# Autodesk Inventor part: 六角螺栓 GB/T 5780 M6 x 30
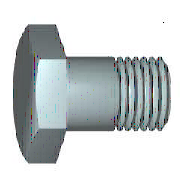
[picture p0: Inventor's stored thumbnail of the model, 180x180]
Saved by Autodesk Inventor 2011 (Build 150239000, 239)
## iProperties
IsCustomPart: 1
Created: 2010-02
Part Number: 六角螺栓 GB/T 5780 M6 x 30
Material: 低炭钢
Description: 六角头螺栓 - 产品等级 C
Document SubType Name: Modeling
Standard: GB/T 5780-2000
Designer: Administrator
Standard Revision: 2000
Standards Organization: GB
Language: zh-CN
Size Designation: M6x30
Categories: <MemberInstance><Categories><Category DisplayName="紧固件" InternalName="e4da775c-781d-43d5-af7c-5136215cf5a6" Mnemonic="FSTN"><Category DisplayName="螺栓" InternalN
Density: 1 g/cm^3
Author: Administrator
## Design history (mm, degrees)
fillet "Fillet2" dims "d71" = 0.25 (= RR)
workplane "Work Plane1"
sketch "Sketch1"
  geometry: L1 (0, 3)-(16, 3); L2 (16, 3)-(16, 0); L3 (16, 0)-(0, 0); L4 (-3.2, 0)-(19.2, 0) reference; L5 (0, -0.6)-(0, 3.6) reference; L6 (0, 3)-(0, 0)
  constraints: 8 end point, 3 point on line, 1 collinear
  dimensions: "d2" = 6 diameter of L1 L3 (= GD); "d59" = 16 distance between parallel lines of L2 L5
revolve "Body" sketch "Sketch1" stored, may be unused: angle "d12" = 90 deg
sketch "Sketch2"
  geometry: L1 (0, 5.774)-(5, 2.887); L2 (5, 2.887)-(5, -2.887); L3 (5, -2.887)-(0, -5.774); L4 (0, -5.774)-(-5, -2.887); L5 (-5, -2.887)-(-5, 2.887); L6 (-5, 2.887)-(0, 5.774); L7 (-7, 0)-(7, 0) reference; L8 (0, 8.083)-(0, -8.083) reference; 2 further points
  constraints: 12 end point, 2 midpoint, 1 coincident, 1 vertical, 11 other
  dimensions: "d11" = 10 distance between parallel lines of L5 L2 (= SW)
extrude "Head" join sketch "Sketch2" distance "d3" = 4 (= KOH); taper "d4" = 0 deg
sketch "Sketch4"
  geometry: L1 (-3.423, 6)-(-4, 5); L2 (-1.1, 0)-(-0.234, 0); L3 (-4.753, 0)-(0.519, 0) reference; L4 (-4, 6)-(-3.423, 6); L5 (-4, 5)-(-4, 6); L6 (0, 7.2)-(0, -1.2) reference
  constraints: 8 end point, 1 parallel, 1 perpendicular, 1 point on line
  dimensions: "d65" = 10 diameter of L1.end L2 (= SW); "d67" = 30 deg angle of L1 L5 (= ANG1); "d68" = 12 diameter of L4 L2 (= 1.2 x SW); "d69" = 4 distance between parallel lines of L5 L6 (= KOH)
revolve "Chamfer1" stored, may be unused: angle "d21" = 90 deg
chamfer "Chamfer2" distance "d6" = 0.61345 (= -0.5 x SPD + 0.5 x GD); stored, may be unused: second distance "d7" = 0.61355 (computed from GUL), angle "d55" = 45 deg
feature "Thread" dims "d15" = 18 (= GEL), "d16" = 0
body "Solid1"
other parameters: "GD" = 6 (= NND) [user parameter; used in 2 equation terms], "BDM" = 6 (= NND) [user parameter], "KOH" = 4 [user parameter; used in 2 equation terms], "GEL" = 18 [user parameter; used in 1 equation term], "SW" = 10 [user parameter; used in 6 equation terms], "SPD" = 4.7731 (= NND - 1.2269 x PTC) [user parameter; used in 1 equation term], "SD2" = 6 (= NND) [user parameter], "SD" = 0 [user parameter], "ANG1" = 30 deg [user parameter; used in 1 equation term], "GAL" = 0.61345 (= 0.61345 x PTC) [user parameter], "GUL" = 0.61345 (= 0.61345 x PTC) [user parameter; used in 1 equation term], "d8" = 0, "RR" = 0.25 [user parameter; used in 1 equation term], "d58" = 0, "RR1" = 0.1 [user parameter], "d73" = 0, "WFT" = 0 [user parameter], "GD1" = 4.7731 (= THREADDIA - 1.2269 x PTC) [user parameter], "THREADDIA" = 6 [user parameter; used in 1 equation term], "TOA" = 30 deg [user parameter], "FAWI" = 90 deg [user parameter], "PTC" = 1 [user parameter; used in 5 equation terms], "NND" = 6 [user parameter; used in 4 equation terms], "E0" = 11.55 (= 1.155 x SW) [user parameter]
